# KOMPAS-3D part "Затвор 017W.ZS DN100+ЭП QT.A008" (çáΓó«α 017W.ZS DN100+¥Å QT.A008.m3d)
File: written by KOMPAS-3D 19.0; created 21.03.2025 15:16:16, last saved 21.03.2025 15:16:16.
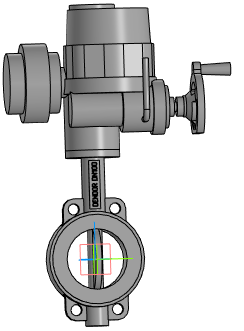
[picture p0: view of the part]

Document properties: Полное имя файла: Затвор 017W.ZS DN100+ЭП QT.A008.a3d

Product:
- Part/product: Затвор 017W.ZS DN100+ЭП QT.A008
    Масса: 43.3441

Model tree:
1. Операция без истории:1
